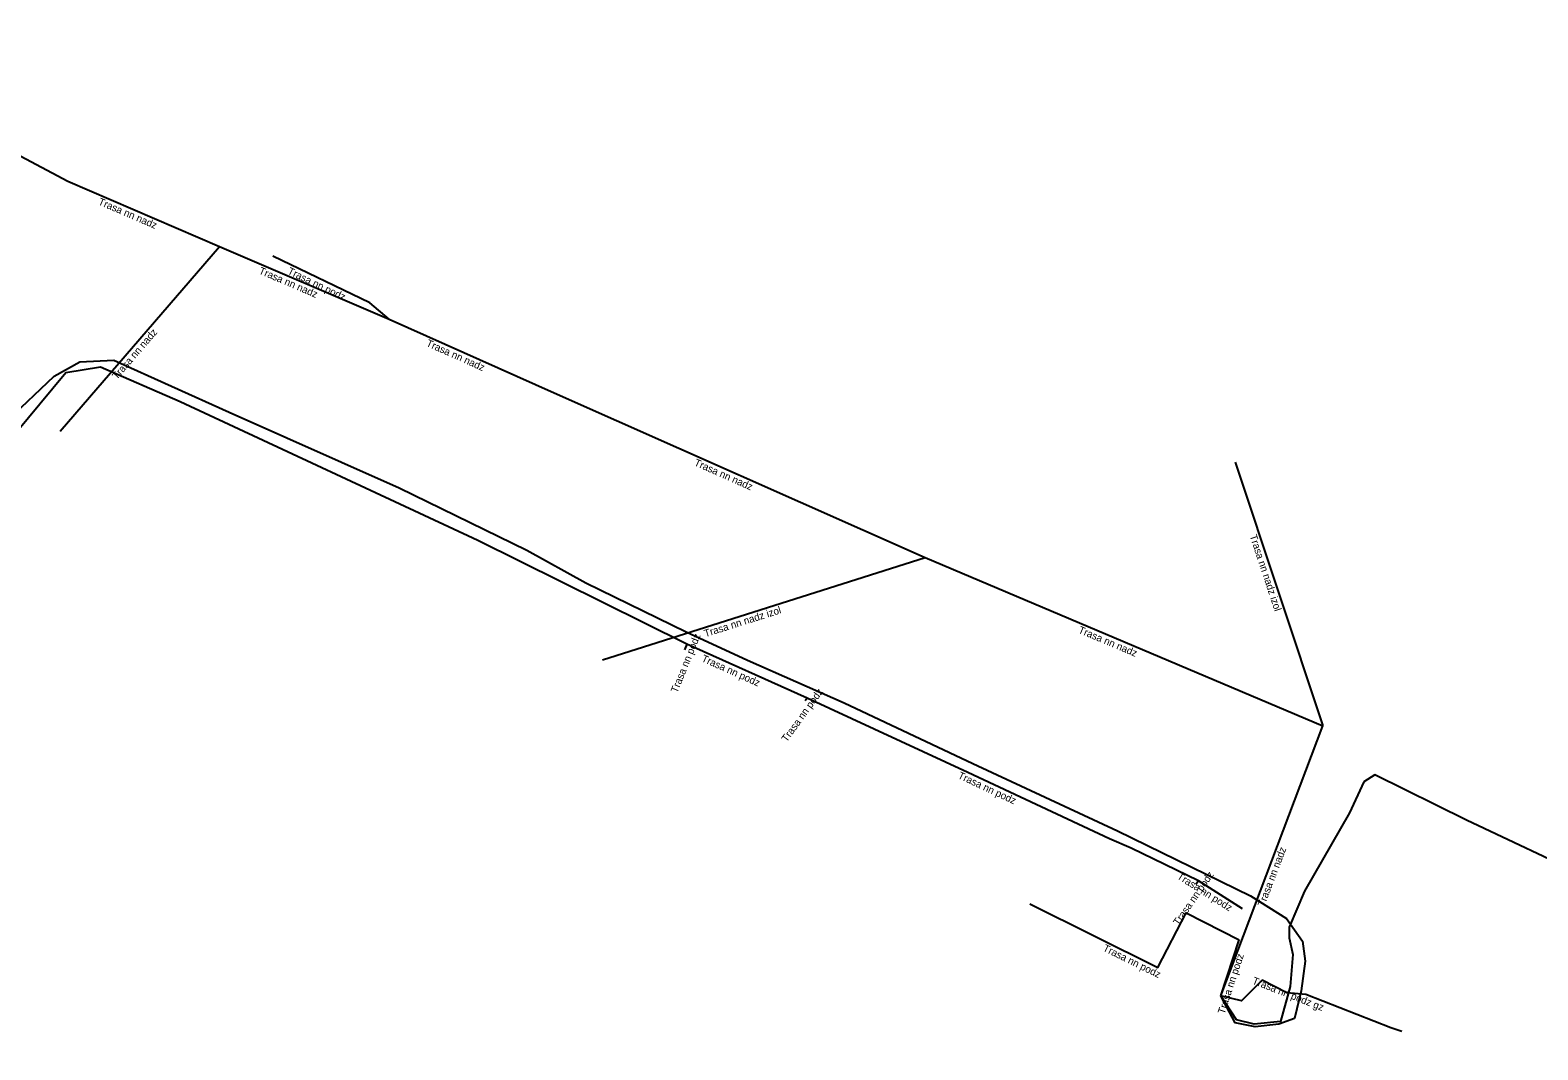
# Model space of a CAD drawing. Extents: x -682739 to -681564, y -1060091 to -1059590.
# Drawn here: x -681899.4 to -681796.6, y -1059959.7 to -1059890.2 of the extents above; entities that cross this region are included whole.
import ezdxf

# ---------------------------------------------------------------- set-up
doc = ezdxf.new("R2010")
doc.units = 0
for name, color, linetype in [('Popiskový text - Ostatní atributy Trasy', 7, 'Continuous'), ('Spojnice NN', 7, 'Continuous'), ('Spojnice VN', 7, 'Continuous')]:
    doc.layers.add(name, color=color, linetype=linetype)

msp = doc.modelspace()

# ---------------------------------------------------------------- linework, layer by layer
at = {"layer": 'Spojnice NN'}
for points in [[(-681916.24, -1059890.21), (-681896.84, -1059900.51)], [(-681896.84, -1059900.51), (-681886.51, -1059904.96)], [(-681897.36, -1059917.54), (-681886.51, -1059904.96)], [(-681886.51, -1059904.96), (-681874.93, -1059909.9)], [(-681874.93, -1059909.9), (-681876.26, -1059908.8), (-681882.88, -1059905.62)], [(-681874.93, -1059909.9), (-681863.7, -1059914.93)], [(-681854.65, -1059932.07), (-681868.9, -1059924.99), (-681889.2, -1059915.54), (-681894.61, -1059913.17), (-681896.98, -1059913.56), (-681901.31, -1059918.77), (-681909.36, -1059927.95), (-681914.13, -1059933.31), (-681915.61, -1059934.19), (-681921.64, -1059942.7), (-681927.57, -1059950.69), (-681930.07, -1059953.8), (-681935.09, -1059957.9), (-681941.05, -1059963.84), (-681947.32, -1059970.93), (-681947.66, -1059971.22), (-681956.6, -1059979.04), (-681961.68, -1059982.03), (-681969.16, -1059983.33), (-681985.27, -1059985.57), (-682009.49, -1059988.61)], [(-681863.7, -1059914.93), (-681838.4, -1059926.16)], [(-681817.26, -1059919.65), (-681811.29, -1059937.63)], [(-681860.39, -1059933.13), (-681838.4, -1059926.16)], [(-681838.4, -1059926.16), (-681811.29, -1059937.63)], [(-681854.65, -1059932.07), (-681854.8, -1059932.44)], [(-681846.45, -1059935.75), (-681854.65, -1059932.07)], [(-681846.45, -1059935.75), (-681846.58, -1059935.93)], [(-681819.77, -1059948.19), (-681824.35, -1059945.97), (-681825.82, -1059945.32), (-681835.49, -1059940.8), (-681846.45, -1059935.75)], [(-681818.25, -1059956.02), (-681811.29, -1059937.63)], [(-681819.77, -1059948.19), (-681819.95, -1059948.45)], [(-681816.76, -1059950.09), (-681819.77, -1059948.19)], [(-681831.26, -1059949.77), (-681822.53, -1059954.09), (-681820.61, -1059950.38), (-681817, -1059952.21)], [(-681818.25, -1059956.02), (-681817, -1059952.21)], [(-681805.91, -1059958.47), (-681806.65, -1059958.21), (-681812.45, -1059955.94), (-681813.75, -1059955.82), (-681815.42, -1059954.96), (-681816.82, -1059956.36), (-681818.25, -1059956.02)]]:
    msp.add_lwpolyline(points, dxfattribs=at)
at = {"layer": 'Spojnice VN'}
for points in [[(-681900.94, -1059916.8), (-681897.79, -1059913.79), (-681896.02, -1059912.81), (-681893.7, -1059912.71), (-681885.85, -1059916.25), (-681874.25, -1059921.41), (-681865.55, -1059925.65), (-681861.54, -1059927.87), (-681854.69, -1059931.21), (-681850.5, -1059933.14), (-681843.92, -1059936.05), (-681835.15, -1059940.2), (-681825.28, -1059944.78), (-681816.22, -1059949.22), (-681813.76, -1059950.76), (-681812.68, -1059952.3), (-681812.49, -1059953.67), (-681812.77, -1059955.68), (-681813.22, -1059957.57), (-681814.28, -1059957.96), (-681815.9, -1059958.15), (-681817.27, -1059957.86), (-681818.25, -1059956.02)], [(-681793.01, -1059948.05), (-681801.49, -1059944.05), (-681807.74, -1059940.96), (-681808.5, -1059941.45), (-681809.47, -1059943.55), (-681812.53, -1059948.89), (-681813.58, -1059951.36), (-681813.57, -1059952.08), (-681813.32, -1059953.22), (-681813.51, -1059955.4), (-681814.16, -1059957.77), (-681815.96, -1059957.96), (-681817.17, -1059957.67), (-681818.25, -1059956.02)]]:
    msp.add_lwpolyline(points, dxfattribs=at)

# ---------------------------------------------------------------- texts
at = {"layer": 'Popiskový text - Ostatní atributy Trasy'}
for s, rotation, p in [('Trasa nn nadz', 336.7171, (-681894.82, -1059902.08)), ('Trasa nn nadz', 336.8474, (-681883.87, -1059906.79)), ('Trasa nn podz', 334.2723, (-681881.91, -1059906.8)), ('Trasa nn nadz', 49.2252, (-681893.5, -1059914.06)), ('Trasa nn nadz', 335.8924, (-681872.46, -1059911.72)), ('Trasa nn nadz', 336.0648, (-681854.19, -1059919.86)), ('Trasa nn nadz izol', 288.3737, (-681816.28, -1059924.68)), ('Trasa nn nadz izol', 17.5914, (-681853.38, -1059931.59)), ('Trasa nn nadz', 337.0672, (-681828, -1059931.27)), ('Trasa nn podz', 67.9321, (-681855.3, -1059935.42)), ('Trasa nn podz', 335.8304, (-681853.69, -1059933.21)), ('Trasa nn podz', 54.1623, (-681847.83, -1059938.77)), ('Trasa nn podz', 334.9474, (-681836.21, -1059941.18)), ('Trasa nn nadz', 69.2576, (-681815.28, -1059950)), ('Trasa nn podz', 55.3048, (-681821.12, -1059951.28)), ('Trasa nn podz', 327.7387, (-681821.27, -1059948.01)), ('Trasa nn podz', 333.6956, (-681826.32, -1059952.94)), ('Trasa nn podz', 71.8307, (-681817.99, -1059957.31)), ('Trasa nn podz gz', 338.6257, (-681816.14, -1059955.19))]:
    msp.add_text(s, height=0.5, rotation=rotation, dxfattribs=at).set_placement(p)

doc.saveas('drawing.dxf')
